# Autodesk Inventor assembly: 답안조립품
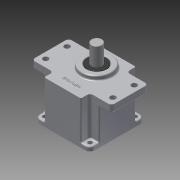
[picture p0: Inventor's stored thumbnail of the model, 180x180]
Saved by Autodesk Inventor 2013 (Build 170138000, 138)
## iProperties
Created: 2015-07
Part Number: 답안조립품
Document SubType Name: Assembly
Designer: user
Author: user
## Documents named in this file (12)
- C:\Users\user\Desktop\450734V1020\답안조립품.iam
- C:\Users\user\Desktop\450734V1020\본체.ipt
- C:\Users\user\Desktop\450734V1020\메인축.ipt
- C:\Users\user\Desktop\450734V1020\서브축.ipt
- C:\Users\user\Desktop\450734V1020\베어링 6003.ipt
- 베어링 6003.ipt
- C:\Users\user\Desktop\450734V1020\베어링 608.ipt
- 베어링 608.ipt
- C:\Users\user\Desktop\450734V1020\오일실 17x32x8.ipt
- C:\Users\user\Desktop\450734V1020\커버.ipt
- C:\Users\user\Desktop\450734V1020\오일실 8x22x7.ipt
- C:\Users\user\Desktop\450734V1020\M4x0.5x16.ipt
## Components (4 placed, 1 different names)
1. M4x0.5x12:1
2. M4x0.5x12:2
3. M4x0.5x12:3
4. M4x0.5x12:4
